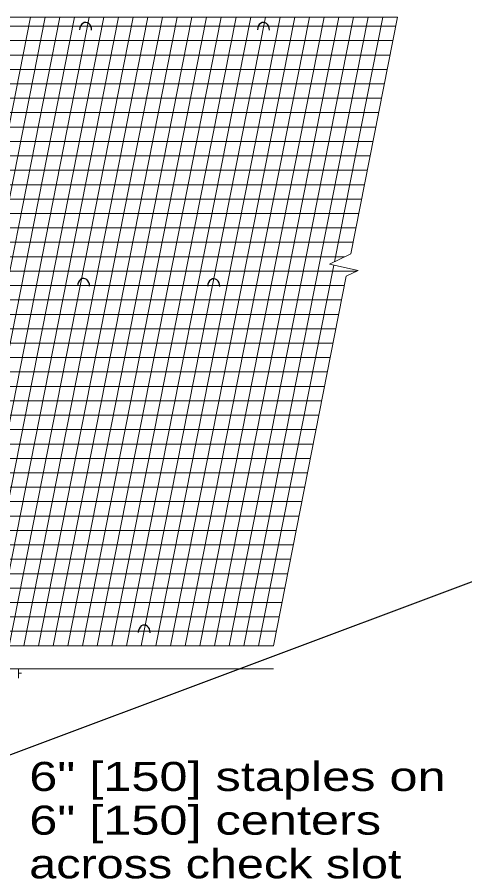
# Model space of a CAD drawing. Extents: x 1083.1 to 1117.1, y 719.4 to 741.4.
# Drawn here: x 1109.844 to 1112.249, y 733.755 to 738.381 of the extents above; entities that cross this region are included whole.
import ezdxf

# ---------------------------------------------------------------- set-up
doc = ezdxf.new("R2010")
doc.units = 0
doc.header["$LTSCALE"] = 0.062
doc.layers.add('1', color=7, linetype='Continuous', lineweight=13)

msp = doc.modelspace()

# ---------------------------------------------------------------- linework, layer by layer
at = {"layer": '1'}
for p, q in [((1109.2485, 735.00583), (1109.91558, 738.38117)), ((1109.2785, 738.38117), (1111.8875, 738.38117)), ((1109.32733, 735.00583), (1109.9945, 738.38117)), ((1109.40625, 735.00583), (1110.07333, 738.38117)), ((1109.48508, 735.00583), (1110.15225, 738.38117)), ((1109.564, 735.00583), (1110.23108, 738.38117)), ((1109.64292, 735.00583), (1110.31, 738.38117)), ((1109.72175, 735.00583), (1110.38883, 738.38117)), ((1109.80067, 735.00583), (1110.46775, 738.38117)), ((1109.8795, 735.00583), (1110.54658, 738.38117)), ((1109.95842, 735.00583), (1110.6255, 738.38117)), ((1110.03725, 735.00583), (1110.70442, 738.38117)), ((1110.11617, 735.00583), (1110.78325, 738.38117)), ((1110.195, 735.00583), (1110.86217, 738.38117)), ((1110.27392, 735.00583), (1110.941, 738.38117)), ((1110.35283, 735.00583), (1111.01992, 738.38117)), ((1110.43167, 735.00583), (1111.09875, 738.38117)), ((1110.51058, 735.00583), (1111.17767, 738.38117)), ((1110.58942, 735.00583), (1111.2565, 738.38117)), ((1110.66833, 735.00583), (1111.33533, 738.38117)), ((1110.74717, 735.00583), (1111.41425, 738.38117)), ((1110.82608, 735.00583), (1111.49308, 738.38117)), ((1110.90492, 735.00583), (1111.572, 738.38117)), ((1110.98383, 735.00583), (1111.65083, 738.38117)), ((1111.06275, 735.00583), (1111.72975, 738.38117)), ((1111.54908, 737.06792), (1111.80858, 738.38117)), ((1111.63625, 737.11008), (1111.8875, 738.38117)), ((1109.269, 738.333), (1111.878, 738.333)), ((1109.25367, 738.25558), (1111.86267, 738.25558)), ((1109.23842, 738.17825), (1111.84742, 738.17825)), ((1109.22308, 738.10092), (1111.83208, 738.10092)), ((1109.20775, 738.0235), (1111.81683, 738.0235)), ((1109.1925, 737.94617), (1111.8015, 737.94617)), ((1109.17717, 737.86875), (1111.78617, 737.86875)), ((1109.16192, 737.79142), (1111.771, 737.79142)), ((1109.14658, 737.714), (1111.75567, 737.714)), ((1109.13125, 737.63667), (1111.74042, 737.63667)), ((1109.11608, 737.55925), (1111.72508, 737.55925)), ((1109.10075, 737.48192), (1111.70983, 737.48192)), ((1109.0855, 737.4045), (1111.6945, 737.4045)), ((1109.07017, 737.32717), (1111.67917, 737.32717)), ((1109.05492, 737.24975), (1111.66392, 737.24975)), ((1109.03958, 737.17242), (1111.64858, 737.17242)), ((1109.02425, 737.095), (1111.60508, 737.095)), ((1111.14158, 735.00583), (1111.54558, 737.05008)), ((1109.009, 737.01767), (1111.6695, 737.01767)), ((1111.2205, 735.00583), (1111.6125, 736.99)), ((1108.99367, 736.94033), (1111.60275, 736.94033)), ((1108.97842, 736.86292), (1111.5875, 736.86292)), ((1108.96308, 736.78558), (1111.57217, 736.78558)), ((1108.94775, 736.70817), (1111.55692, 736.70817)), ((1108.93258, 736.63083), (1111.54158, 736.63083)), ((1108.91725, 736.55342), (1111.52633, 736.55342)), ((1108.902, 736.47608), (1111.511, 736.47608)), ((1108.88667, 736.39867), (1111.49575, 736.39867)), ((1108.87133, 736.32133), (1111.48042, 736.32133)), ((1108.85608, 736.24392), (1111.46508, 736.24392)), ((1108.84075, 736.16658), (1111.44983, 736.16658)), ((1108.8255, 736.08917), (1111.4345, 736.08917)), ((1108.81017, 736.01183), (1111.41933, 736.01183)), ((1108.79483, 735.9345), (1111.404, 735.9345)), ((1108.77958, 735.85708), (1111.38875, 735.85708)), ((1108.76433, 735.77975), (1111.37342, 735.77975)), ((1108.74908, 735.70233), (1111.35817, 735.70233)), ((1108.73375, 735.625), (1111.34283, 735.625)), ((1108.7185, 735.54758), (1111.3275, 735.54758)), ((1108.70317, 735.47025), (1111.31225, 735.47025)), ((1108.68783, 735.39283), (1111.29692, 735.39283)), ((1108.67258, 735.3155), (1111.28167, 735.3155)), ((1108.65725, 735.23808), (1111.26633, 735.23808)), ((1108.642, 735.16075), (1111.25108, 735.16075)), ((1108.62667, 735.08333), (1111.23583, 735.08333)), ((1108.61133, 735.00583), (1111.2205, 735.00583)), ((1108.66133, 734.88167), (1111.2205, 734.88167)), ((1109.85083, 734.83175), (1109.85083, 734.88167)), ((1109.85083, 734.88167), (1109.88333, 734.88167)), ((1109.85083, 734.85833), (1109.86817, 734.85833)), ((1109.85083, 734.835), (1109.853, 734.835))]:
    msp.add_line(p, q, dxfattribs=at)
at = {"layer": '1', "lineweight": 25}
msp.add_line((1108.8655, 734.06875), (1112.81717, 735.54867), dxfattribs=at)
at = {"layer": '1'}
msp.add_lwpolyline([(1111.63625, 737.11008), (1111.5225, 737.05508), (1111.67708, 737.02133), (1111.6125, 736.99)], dxfattribs=at)
at = {"layer": '1', "lineweight": 25}
for centre, major_axis, start_param, end_param in [((1110.212, 738.31247), (0.00099, 0.04097), 4.7123995, 7.8539922), ((1111.16722, 738.31247), (0.00099, 0.04097), 4.7123995, 7.8539922), ((1110.2004, 736.93742), (0.00106, 0.04097), 4.7124002, 7.8539929), ((1110.90007, 736.93575), (0.00106, 0.04097), 4.7124002, 7.8539929), ((1110.52627, 735.07617), (0.00099, 0.04097), 4.7123995, 7.8539922)]:
    msp.add_ellipse(centre, major_axis=major_axis, ratio=0.78812, start_param=start_param, end_param=end_param, dxfattribs=at)

# ---------------------------------------------------------------- texts
at = {"layer": '1'}
for s, width, p in [('6" [150] staples on', 1.3, (1109.909, 734.22608)), ('6" [150] centers', 1.3, (1109.909, 733.99142)), ('across check slot', 1.25, (1109.909, 733.75675))]:
    msp.add_text(s, height=0.156, dxfattribs=dict(at, width=width)).set_placement(p)

doc.saveas('drawing.dxf')
